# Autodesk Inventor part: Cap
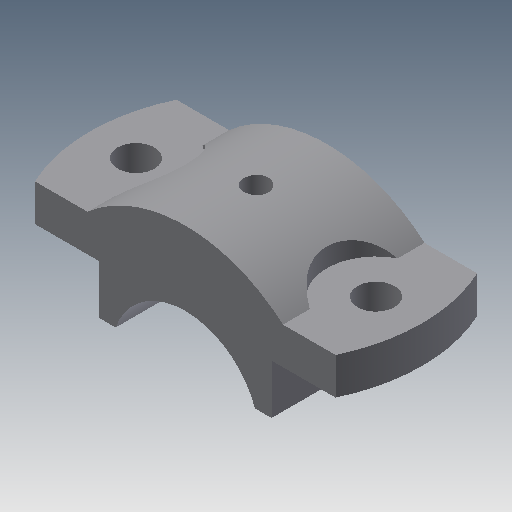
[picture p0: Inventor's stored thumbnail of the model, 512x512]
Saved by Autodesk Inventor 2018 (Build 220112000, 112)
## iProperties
Created: 2009-04
Part Number: Cap
Document SubType Name: Modeling
Designer: Sham
Density: 1 g/cm^3
Material: Generic
Appearance: Default
Author: Sham
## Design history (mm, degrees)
sketch "Sketch1"
  geometry: L1 (-48.857, 23)-(48.857, 23); L2 (48.857, -23)-(-48.857, -23); A1 r 54 centre (0, 0) between (-48.857, 23) and (-48.857, -23); A2 r 54 centre (0, 0) between (48.857, -23) and (48.857, 23); 1 further point
  constraints: 4 end point, 4 point on circle, 2 centre point, 2 coincident, 1 horizontal, 1 parallel, 1 other
  dimensions: "d3" = 54 radius of A1; "d4" = 54 radius of A2; "d5" = 46 distance between parallel lines of L2 L1; "d6" = 23 distance from line of point (0, 0) L1
extrude "Extrusion1" new body sketch "Sketch1" distance "d7" = 12; taper "d8" = 0 deg
sketch "Sketch3"
  geometry: L1 (20.906, 0)-(20.906, -16); L2 (76.906, -0.137)-(76.906, -16.137); L3 (20.906, -16)-(26.23, -16); L4 (71.532, -16.137)-(76.906, -16.137); L5 (76.906, -0.137)-(76.857, 12); L6 (97.714, 0)-(0, 0) reference; L7 (76.857, 12)-(80.606, 12); L8 (17.108, 12)-(20.906, 12); L9 (20.906, 12)-(20.906, 0); L10 (0, 12)-(97.714, 12) reference; A1 r 24 centre (48.857, -24) between (71.532, -16.137) and (26.23, -16); A2 r 48 centre (48.857, -24) between (80.606, 12) and (17.108, 12); 3 further points
  constraints: 16 end point, 4 point on circle, 3 parallel, 3 perpendicular, 2 centre point, 2 coincident, 2 vertical alignment, 1 collinear, 1 midpoint, 1 vertical, 2 other
  dimensions: "d17" = 48 diameter of A1; "d18" = 16 distance of L1.start L1.end; "d19" = 56 distance between parallel lines of L2 L1; "d21" = 8 vertical distance of A1.centre L1.end; "d22" = 48 radius of A2; "d23" = 0 distance from line of L6 L1.start; "d38" = 31.74902 distance of L7.end point (48.857, 12); "d39" = 28 distance from line of point (48.857, 12) L5
extrude "Extrusion2" join sketch "Sketch3" stored distance "d24" = 12; taper "d25" = 0 deg
sketch "Sketch4"
  geometry: 2 further points
  dimensions: "d26" = 78 distance of point (39, 0) point (-39, 0)
hole "Hole1" sketch "Sketch4" at (-39, 0), (39, 0) diameter "d28" = 12; stored, may be unused: countersink angle "d32" = 90 deg, drill point angle "d34" = 118 deg; dims "d29" = 6, "d30" = 4, "d31" = 2, "d33" = 8
sketch "Sketch5"
  geometry: L1 (-31.749, -23)-(-31.749, 23) reference; L2 (-31.749, 14.263)-(-31.749, -14.263); C1 r 6 at (-39, 0) reference; A1 r 16 centre (-39, 0) between (-31.749, -14.263) and (-31.749, 14.263)
  constraints: 2 end point, 2 point on circle, 1 centre point, 1 coincident, 1 collinear, 1 point on line
  dimensions: "d35" = 16 radius of A1
extrude "Extrusion3" cut sketch "Sketch5" distance "d36" = 12; taper "d37" = 0 deg
mirror "Mirror2"
workplane "Work Plane4"
sketch "Sketch6"
  geometry: L1 (-31.749, 0)-(31.749, 0) reference; 1 further point
  dimensions: "d40" = 23 distance from line of L1 point (0, 23)
hole "Hole2" sketch "Sketch6" at (0, 23) diameter "d41" = 6; stored, may be unused: countersink angle "d45" = 90 deg, drill point angle "d47" = 118 deg; dims "d42" = 6, "d43" = 8, "d44" = 16, "d46" = 8
body "Solid1"
